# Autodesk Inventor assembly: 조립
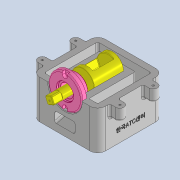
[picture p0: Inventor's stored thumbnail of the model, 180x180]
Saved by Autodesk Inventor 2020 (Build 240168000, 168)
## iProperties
Created: 2022-03
Part Number: 조립
Document SubType Name: Assembly
Designer: Administrator
Author: Administrator
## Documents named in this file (5)
- C:\Users\Administrator\Desktop\720306V1011\조립.iam
- C:\Users\Administrator\Desktop\720306V1011\본체.ipt
- C:\Users\Administrator\Desktop\720306V1011\본체커버.ipt
- C:\Users\Administrator\Desktop\720306V1011\앞커버.ipt
- C:\Users\Administrator\Desktop\720306V1011\핸들축.ipt
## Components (1 placed, 1 different names)
1. 핸들축:1
